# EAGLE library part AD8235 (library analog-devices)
40 ?A Micropower Instrumentation Amplifier in WLCSP Package Source: http://www.analog.com/static/imported-files/data_sheets/AD8235.pdf
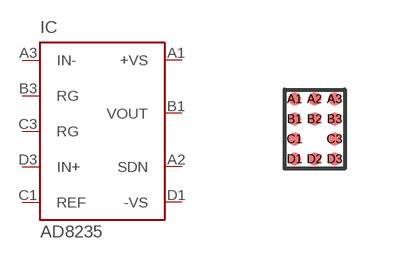
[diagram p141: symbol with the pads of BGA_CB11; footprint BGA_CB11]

Designator prefix IC

## AD8235 (MPN: AD8235ACBZ-P7; OC_FARNELL: 1827361; OC_NEWARK: 35R0266)  [BGA_CB11]
A1  +VS  pwr
A2  SDN  pas
A3  IN-  in
B1  VOUT  out
B3  RG  in
C1  REF  in
C3  RG  in
D1  -VS  pwr
D3  IN+  in

## Footprint BGA_CB11 (pad centres in mm)
11-Ball, Backside-Coated, Wafer Level Chip Scale Package WLCSP CB-11-1 Source: http://www.analog.com/static/imported-files/data_sheets/AD8235.pdf
smd 0.33 x 0.33: A1 -0.5,0.75; A2 0,0.75; A3 0.5,0.75; B1 -0.5,0.25; B2 0,0.25; B3 0.5,0.25; C1 -0.5,-0.25; C3 0.5,-0.25; D1 -0.5,-0.75; D2 0,-0.75; D3 0.5,-0.75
